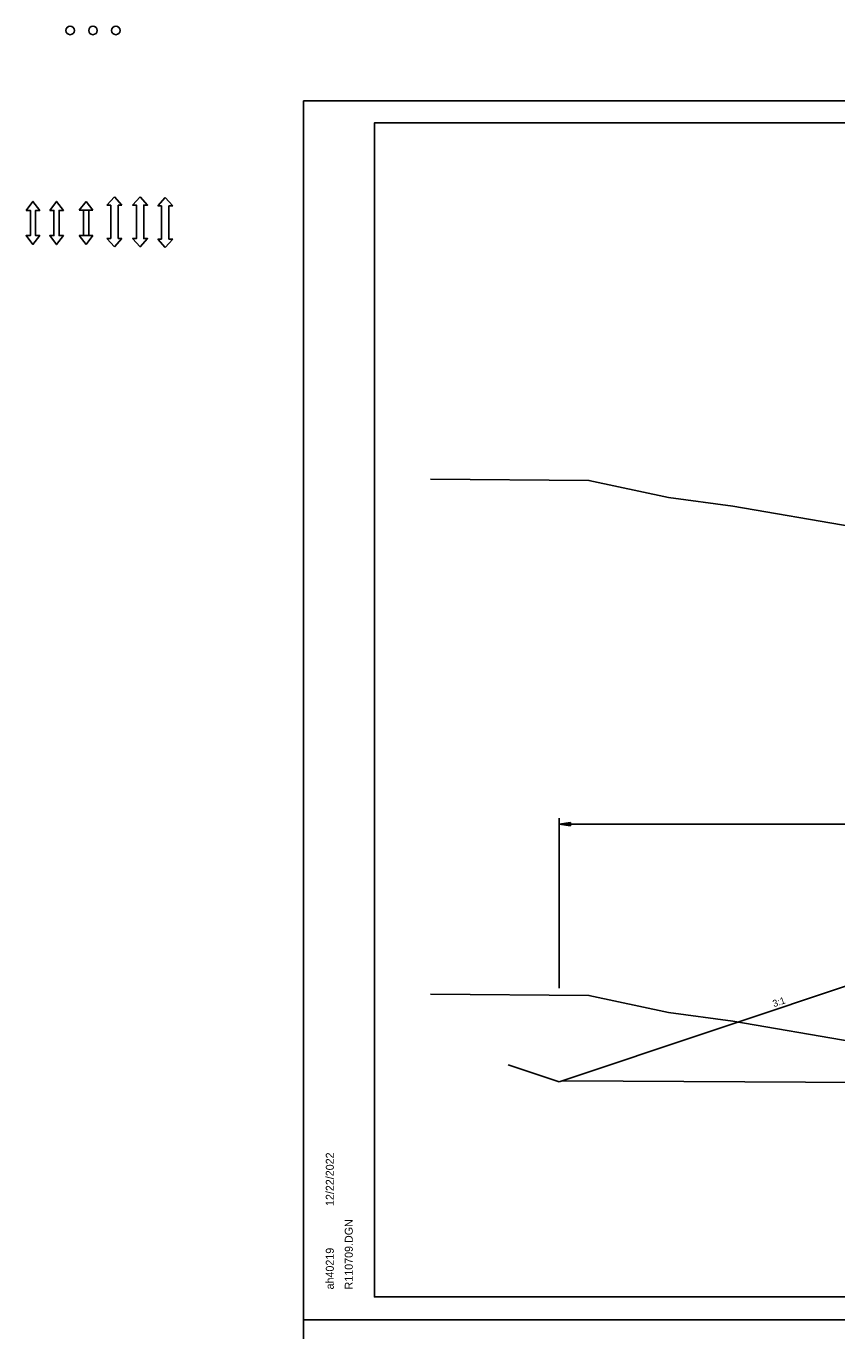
# Model space of a CAD drawing. Extents: x 2829243 to 2838161, y 467639 to 474695.
# Drawn here: x 2829243 to 2829953, y 472569 to 473710 of the extents above; entities that cross this region are included whole.
import ezdxf

# ---------------------------------------------------------------- set-up
doc = ezdxf.new("R2010")
doc.units = 0
for name, color, linetype in [('Default', 7, 'Continuous'), ('R_Border', 7, 'Continuous'), ('R_Border Notes', 7, 'Continuous'), ('R_Dimension', 7, 'Continuous'), ('R_Draft', 7, 'Continuous'), ('R_Exist Surface', 7, 'Continuous'), ('R_Fin Surface', 7, 'Continuous'), ('R_MOT', 7, 'Continuous'), ('R_No Plot', 7, 'Continuous'), ('R_Striping', 7, 'Continuous'), ('R_Water', 7, 'Continuous')]:
    doc.layers.add(name, color=color, linetype=linetype)

msp = doc.modelspace()

# ---------------------------------------------------------------- linework, layer by layer
at = {"layer": 'Default'}
msp.add_lwpolyline([(2829343.1, 473561), (2829336.5, 473553.8), (2829339.8, 473553.8), (2829339.8, 473524.4), (2829336.5, 473524.4), (2829343.1, 473517.3), (2829349.6, 473524.4), (2829346.3, 473524.4), (2829346.3, 473553.8), (2829349.6, 473553.8)], close=True, dxfattribs=at)
at = {"layer": 'R_Border'}
for p, q in [((2829548.2, 473625.7), (2831129.1, 473625.7)), ((2829548.2, 472598.4), (2829548.2, 473625.7)), ((2829548.2, 472598.4), (2829548.2, 472598.4)), ((2831129.1, 472598.4), (2829548.2, 472598.4))]:
    msp.add_line(p, q, dxfattribs=at)
at = {"layer": 'R_Border Notes'}
for p, q in [((2829358.5, 473553.1), (2829365, 473560.3)), ((2829361.7, 473553.1), (2829358.5, 473553.1)), ((2829361.7, 473523.8), (2829361.7, 473553.1)), ((2829365, 473560.3), (2829371.6, 473553.1)), ((2829371.6, 473553.1), (2829368.3, 473553.1)), ((2829368.3, 473553.1), (2829368.3, 473523.8)), ((2829365, 473516.6), (2829358.5, 473523.8)), ((2829358.5, 473523.8), (2829361.7, 473523.8)), ((2829371.6, 473523.8), (2829365, 473516.6)), ((2829368.3, 473523.8), (2829371.6, 473523.8))]:
    msp.add_line(p, q, dxfattribs=at)
at = {"layer": 'R_Dimension'}
for p, q in [((2829709.9, 472868.5), (2829709.9, 473017.2)), ((2829719.9, 473013.5), (2829709.9, 473012)), ((2830400.8, 473012), (2829709.9, 473012)), ((2829719.9, 473010.5), (2829709.9, 473012)), ((2829719.9, 473013.2), (2829711.5, 473012)), ((2829719.9, 473010.7), (2829711.5, 473012)), ((2829719.9, 473013), (2829713.3, 473012)), ((2829719.9, 473011), (2829713.3, 473012)), ((2829719.9, 473012.7), (2829714.9, 473012)), ((2829719.9, 473011.2), (2829714.9, 473012)), ((2829719.9, 473012.5), (2829716.6, 473012)), ((2829719.9, 473011.5), (2829716.6, 473012)), ((2829719.9, 473012.2), (2829718.3, 473012)), ((2829719.9, 473011.7), (2829718.3, 473012)), ((2829719.9, 473010.5), (2829719.9, 473013.5))]:
    msp.add_line(p, q, dxfattribs=at)
at = {"layer": 'R_Exist Surface'}
for points in [[(2829597.2, 473314), (2829735.9, 473312.9), (2829805.6, 473298), (2829861.9, 473290.3), (2829967.2, 473272.3)], [(2829597.2, 472863.4), (2829735.9, 472862.3), (2829805.6, 472847.4), (2829861.9, 472839.7), (2829967.2, 472821.7)]]:
    msp.add_lwpolyline(points, dxfattribs=at)
at = {"layer": 'R_Fin Surface'}
msp.add_line((2829665.1, 472801.6), (2829709.9, 472786.7), dxfattribs=at)
msp.add_lwpolyline([(2829709.9, 472786.7), (2829980.8, 472877), (2830001.3, 472880.4), (2830100.8, 472897)], dxfattribs=at)
at = {"layer": 'R_MOT'}
for p, q in [((2829320.6, 473561), (2829314, 473553.8)), ((2829317.3, 473553.8), (2829314, 473553.8)), ((2829317.3, 473553.8), (2829317.3, 473524.4)), ((2829327.1, 473553.8), (2829320.6, 473561)), ((2829323.9, 473553.8), (2829323.9, 473524.4)), ((2829323.9, 473553.8), (2829327.1, 473553.8)), ((2829317.3, 473524.4), (2829314, 473524.4)), ((2829320.6, 473517.3), (2829314, 473524.4)), ((2829327.1, 473524.4), (2829320.6, 473517.3)), ((2829323.9, 473524.4), (2829327.1, 473524.4))]:
    msp.add_line(p, q, dxfattribs=at)
msp.add_lwpolyline([(2829263.9, 473549.1), (2829267.6, 473549.1), (2829267.6, 473527), (2829263.9, 473527), (2829269.9, 473519.2), (2829275.9, 473527), (2829272.1, 473527), (2829272.1, 473549.1), (2829275.9, 473549.1), (2829269.9, 473556.9)], close=True, dxfattribs=at)
for centre in [(2829281.8, 473706.6), (2829301.8, 473706.6), (2829321.8, 473706.6)]:
    msp.add_circle(centre, 3.75, dxfattribs=at)
at = {"layer": 'R_No Plot'}
for p, q in [((2829486.2, 473645.1), (2831152.9, 473645.1)), ((2829486.2, 472578.5), (2831152.9, 472578.5)), ((2829486.2, 472578.4), (2831152.9, 472578.4))]:
    msp.add_line(p, q, dxfattribs=at)
for points in [[(2829486.2, 473645.1), (2831152.9, 473645.1), (2831152.9, 472578.4), (2829486.2, 472578.4)], [(2830717.8, 473625.7), (2830815.9, 473625.7), (2830815.9, 473576.3), (2830896.5, 473576.3), (2831012.5, 473576.3), (2831012.5, 473454.6), (2831129.1, 473454.6), (2831129.1, 472598.4), (2829548.2, 472598.4), (2829548.2, 473625.7)], [(2829486.2, 472578.4), (2831152.9, 472578.4), (2831152.9, 471511.8), (2829486.2, 471511.8)]]:
    msp.add_lwpolyline(points, close=True, dxfattribs=at)
at = {"layer": 'R_Striping'}
for p, q in [((2829289.8, 473549.2), (2829295.8, 473557)), ((2829295.8, 473557), (2829301.8, 473549.2)), ((2829289.8, 473549.2), (2829293.6, 473549.2)), ((2829293.6, 473549.2), (2829293.6, 473527.1)), ((2829293.6, 473527.1), (2829293.6, 473549.2)), ((2829298.1, 473549.2), (2829293.6, 473549.2)), ((2829298.1, 473549.2), (2829298.1, 473527.1)), ((2829298.1, 473549.2), (2829301.8, 473549.2)), ((2829298.1, 473527.1), (2829298.1, 473549.2)), ((2829293.6, 473527.1), (2829289.8, 473527.1)), ((2829295.8, 473519.3), (2829289.8, 473527.1)), ((2829293.6, 473527.1), (2829298.1, 473527.1)), ((2829301.8, 473527.1), (2829295.8, 473519.3)), ((2829301.8, 473527.1), (2829298.1, 473527.1))]:
    msp.add_line(p, q, dxfattribs=at)
msp.add_lwpolyline([(2829243.2, 473549.1), (2829249.2, 473556.9), (2829255.2, 473549.1), (2829251.5, 473549.1), (2829251.5, 473527.1), (2829255.2, 473527.1), (2829249.2, 473519.3), (2829243.2, 473527.1), (2829247, 473527.1), (2829247, 473549.1)], close=True, dxfattribs=at)
at = {"layer": 'R_Water'}
msp.add_line((2829712.4, 472787.6), (2830423.2, 472783.6), dxfattribs=at)

# ---------------------------------------------------------------- texts
at = {"layer": 'R_Border'}
for s, p in [('12/22/2022', (2829512.6, 472678)), ('R110709.DGN', (2829529.2, 472605)), ('ah40219', (2829512.6, 472605))]:
    msp.add_text(s, height=7, rotation=90, dxfattribs=at).set_placement(p)
at = {"layer": 'R_Draft'}
msp.add_text('3:1', height=6, rotation=18.4349, dxfattribs=at).set_placement((2829897.9, 472851.9))

doc.saveas('drawing.dxf')
